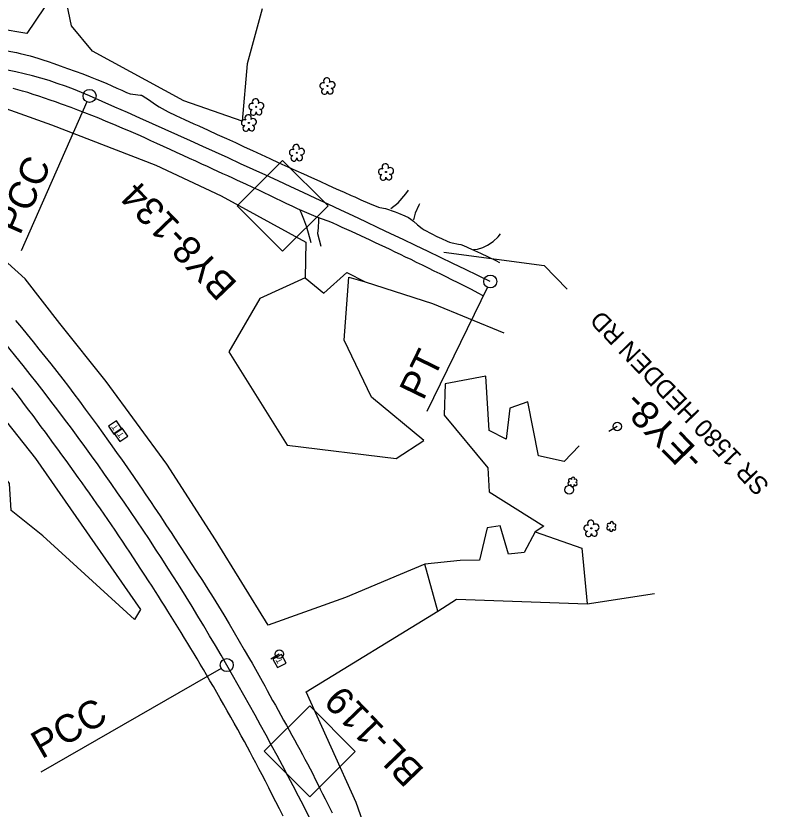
# Model space of a CAD drawing. Extents: x 473158 to 477500, y 500738 to 505114.
# Drawn here: x 475555.3 to 475990, y 502265.8 to 502723.9 of the extents above; entities that cross this region are included whole.
import ezdxf

# ---------------------------------------------------------------- set-up
doc = ezdxf.new("R2010")
doc.units = 0
for name, color, linetype in [('CTL Secondary Horizontal and Vertical CELL', 7, 'Continuous'), ('CTL Secondary Horizontal and Vertical Leader', 7, 'Continuous'), ('CTL Secondary Horizontal and Vertical Text', 7, 'Continuous'), ('Exist Horizontal Alignment', 7, 'Continuous'), ('Exist Horizontal Alignment Direction Label', 7, 'Continuous'), ('Exist Other Culture Well CELL', 7, 'Continuous'), ('Exist Roads EOP', 7, 'Continuous'), ('Exist Roads EOP Text', 7, 'Continuous'), ('Exist Roads Soil', 7, 'Continuous'), ('Exist Utilities Power Pole CELL', 7, 'Continuous'), ('Exist Utilities Telephone Pedestal CELL', 7, 'Continuous'), ('Exist Vegetation Hedge Row', 7, 'Continuous'), ('Exist Vegetation Shrub CELL', 7, 'Continuous'), ('Exist Vegetation Tree CELL', 7, 'Continuous'), ('Exist Vegetation Woods Line', 7, 'Continuous')]:
    doc.layers.add(name, color=color, linetype=linetype)

msp = doc.modelspace()

# ---------------------------------------------------------------- linework, layer by layer
at = {"layer": 'CTL Secondary Horizontal and Vertical CELL'}
for p, q in [((475709.09, 502614.11), (475709.09, 502614.11)), ((475724.77, 502299.1), (475724.77, 502299.1))]:
    msp.add_line(p, q, dxfattribs=at)
for points in [[(475683.01, 502614.2), (475709.22, 502640.4), (475735.47, 502614.15), (475709.26, 502587.94)], [(475698.7, 502299.19), (475724.9, 502325.39), (475751.16, 502299.14), (475724.95, 502272.93)]]:
    msp.add_lwpolyline(points, close=True, dxfattribs=at)
at = {"layer": 'CTL Secondary Horizontal and Vertical Leader'}
msp.add_lwpolyline([(475802.27, 502587.46), (475860.17, 502579.73), (475873.39, 502565.98)], dxfattribs=at)
at = {"layer": 'Exist Horizontal Alignment'}
for p, q in [((475596.32, 502674.23), (475558.36, 502588.14)), ((475827.45, 502567.1), (475792.56, 502495.4)), ((475673.81, 502347.07), (475569.78, 502287.2))]:
    msp.add_line(p, q, dxfattribs=at)
for centre in [(475597.83, 502677.66), (475829.09, 502570.47), (475677.06, 502348.94)]:
    msp.add_circle(centre, 3.75, dxfattribs=at)
for centre, radius, start, end in [((475506.78, 502471.14), 225.7, 66.2091, 86.4527), ((472863.49, 496475.42), 6778.23, 64.054428, 66.209138), ((474463.75, 501650.77), 1399.85, 29.91717, 47.05976), ((473989.37, 501377.8), 1947.16, 23.67637, 29.91717)]:
    msp.add_arc(centre, radius, start, end, dxfattribs=at)
at = {"layer": 'Exist Other Culture Well CELL'}
msp.add_circle((475874.64, 502450.21), 2.56, dxfattribs=at)
at = {"layer": 'Exist Roads EOP'}
for points in [[(475550.28, 502703.71), (475555.6, 502702.62), (475557.78, 502702.16), (475563.57, 502700.75), (475568.08, 502699.39), (475570.86, 502698.49), (475573.95, 502697.47), (475577.27, 502696.34), (475580.97, 502695.05), (475585.2, 502693.53), (475589.63, 502691.91), (475593.94, 502690.31), (475598.1, 502688.72), (475602.09, 502687.14), (475607.5, 502684.91), (475610.64, 502683.55), (475613.64, 502682.2), (475616.42, 502680.91), (475619.11, 502679.68), (475621.33, 502678.9), (475622.88, 502678.57), (475627.31, 502678.15), (475627.63, 502678.09), (475627.8, 502678.03), (475628.19, 502677.86), (475632.36, 502675.11), (475635.29, 502673.1), (475638.05, 502671.3), (475643.15, 502668.45), (475647.7, 502666.23), (475652.66, 502664), (475658.08, 502661.6), (475660.85, 502660.36), (475666.25, 502657.88), (475671.56, 502655.43), (475676.86, 502653.02), (475682.05, 502650.64), (475687.07, 502648.31), (475691.97, 502646.02), (475696.83, 502643.75), (475701.83, 502641.44), (475707.14, 502639), (475712.32, 502636.64), (475716.94, 502634.56), (475721.37, 502632.56), (475725.99, 502630.47), (475730.73, 502628.32), (475735.53, 502626.17), (475740.23, 502624.07), (475744.71, 502622.06), (475748.89, 502620.17), (475750.84, 502619.29), (475754.43, 502617.66), (475759.41, 502615.45), (475764.5, 502613.44), (475765.33, 502613.22), (475768.69, 502612.64), (475774.15, 502610.73), (475776.13, 502609.95), (475779.72, 502608.42), (475781.92, 502607.33), (475783.3, 502606.47), (475784.88, 502605.27), (475787.13, 502603.28), (475789.77, 502601.03), (475791.02, 502600.24), (475795.34, 502598.04), (475798.34, 502596.51), (475800.92, 502595.23), (475804.19, 502593.68), (475805.63, 502593.13), (475807.03, 502592.74), (475810.8, 502592.09), (475812.1, 502591.76), (475813.68, 502591.24), (475818.24, 502589.21), (475823.54, 502586.75), (475827.94, 502584.67), (475832.32, 502582.54), (475834.5, 502581.47)], [(475825, 502562.27), (475822.2, 502563.71), (475818.23, 502565.76), (475814.34, 502567.75), (475810.6, 502569.65), (475807, 502571.46), (475803.55, 502573.18), (475800.17, 502574.85), (475796.78, 502576.52), (475793.38, 502578.19), (475789.97, 502579.86), (475786.61, 502581.5), (475783.37, 502583.08), (475780.24, 502584.59), (475777.22, 502586.04), (475774.26, 502587.45), (475771.31, 502588.85), (475768.36, 502590.24), (475765.42, 502591.62), (475762.53, 502592.98), (475759.71, 502594.29), (475754.31, 502596.81), (475749.03, 502599.25), (475743.69, 502601.71), (475741.27, 502602.83), (475738.03, 502604.31), (475735.61, 502605.36), (475731.67, 502606.61), (475728.59, 502607.8), (475723.21, 502610.1), (475717.75, 502612.5), (475714.76, 502613.88), (475711.69, 502615.33), (475708.54, 502616.82), (475705.28, 502618.4), (475701.94, 502620.06), (475698.7, 502621.63), (475695.52, 502623.12), (475691.99, 502624.76), (475687.98, 502626.62), (475683.19, 502628.83), (475680.48, 502630.08), (475677.64, 502631.39), (475674.77, 502632.71), (475671.86, 502634.04), (475668.91, 502635.39), (475665.85, 502636.8), (475662.6, 502638.29), (475659.17, 502639.87), (475655.55, 502641.53), (475651.83, 502643.25), (475648.07, 502644.98), (475644.28, 502646.73), (475640.45, 502648.49), (475636.74, 502650.19), (475633.29, 502651.75), (475630.11, 502653.19), (475627.19, 502654.49), (475621.78, 502656.87), (475616.69, 502659.06), (475611.91, 502661.08), (475607.41, 502662.95), (475603.15, 502664.7), (475599.08, 502666.33), (475595.11, 502667.88), (475591.17, 502669.4), (475587.29, 502670.86), (475581.7, 502672.93), (475578.28, 502674.16), (475575.12, 502675.25), (475571.9, 502676.33), (475568.6, 502677.43), (475565.35, 502678.5), (475562.2, 502679.54), (475559.17, 502680.45), (475553.7, 502681.87)], [(475555.07, 502548.03), (475558.49, 502543.9), (475561.88, 502539.79), (475565.27, 502535.64), (475568.65, 502531.45), (475572.03, 502527.23), (475575.46, 502522.93), (475578.97, 502518.48), (475582.42, 502514.06), (475585.63, 502509.85), (475588.77, 502505.65), (475592, 502501.31), (475595.32, 502496.81), (475598.73, 502492.16), (475602.14, 502487.48), (475605.45, 502482.9), (475608.84, 502478.18), (475610.63, 502475.66), (475612.49, 502473.05), (475614.36, 502470.41), (475616.19, 502467.83), (475617.97, 502465.3), (475619.71, 502462.82), (475623.12, 502457.9), (475626.51, 502452.97), (475628.2, 502450.48), (475629.91, 502447.95), (475631.64, 502445.4), (475633.39, 502442.81), (475635.14, 502440.21), (475636.87, 502437.63), (475638.58, 502435.08), (475640.27, 502432.54), (475641.95, 502430.01), (475643.61, 502427.49), (475645.26, 502424.96), (475646.88, 502422.43), (475650.12, 502417.41), (475653.33, 502412.48), (475656.53, 502407.58), (475659.74, 502402.68), (475662.94, 502397.77), (475666.13, 502392.85), (475669.26, 502387.92), (475672.34, 502382.96), (475675.36, 502377.94), (475678.35, 502372.82), (475681.3, 502367.73), (475684.18, 502362.76), (475687.08, 502357.78), (475690.08, 502352.64), (475691.59, 502350.03), (475694.54, 502344.84), (475697.43, 502339.64), (475698.91, 502336.97), (475700.41, 502334.23), (475701.95, 502331.42), (475703.51, 502328.58), (475705.08, 502325.74), (475706.65, 502322.89), (475708.24, 502320.04), (475709.84, 502317.18), (475711.42, 502314.32), (475713.01, 502311.45), (475714.6, 502308.58), (475716.16, 502305.73), (475717.7, 502302.92), (475719.21, 502300.15), (475720.69, 502297.42), (475722.15, 502294.68), (475723.63, 502291.88), (475725.11, 502289.01), (475726.6, 502286.09), (475728.08, 502283.15), (475729.54, 502280.26), (475730.96, 502277.4), (475732.36, 502274.58), (475733.74, 502271.79), (475735.11, 502269.02), (475736.48, 502266.28), (475737.85, 502263.56)], [(475709.55, 502261.7), (475707.42, 502265.91), (475705.32, 502270.05), (475703.25, 502274.11), (475701.24, 502278.04), (475699.29, 502281.85), (475697.39, 502285.54), (475695.55, 502289.08), (475693.8, 502292.44), (475692.12, 502295.62), (475690.53, 502298.62), (475688.91, 502301.62), (475687.18, 502304.81), (475685.33, 502308.19), (475683.36, 502311.74), (475681.34, 502315.38), (475679.31, 502318.98), (475677.29, 502322.55), (475675.28, 502326.09), (475673.27, 502329.6), (475671.27, 502333.08), (475669.3, 502336.52), (475667.33, 502339.93), (475665.4, 502343.26), (475663.53, 502346.47), (475661.7, 502349.56), (475659.93, 502352.53), (475658.16, 502355.46), (475656.35, 502358.45), (475654.5, 502361.49), (475652.6, 502364.58), (475650.69, 502367.7), (475648.77, 502370.82), (475646.86, 502373.92), (475644.94, 502377.02), (475643.05, 502380.07), (475641.21, 502383.03), (475639.41, 502385.89), (475637.66, 502388.67), (475635.87, 502391.48), (475633.95, 502394.47), (475631.9, 502397.63), (475629.73, 502400.97), (475627.5, 502404.36), (475625.31, 502407.69), (475623.16, 502410.95), (475621.04, 502414.16), (475618.94, 502417.32), (475616.84, 502420.48), (475614.73, 502423.64), (475612.62, 502426.78), (475610.5, 502429.91), (475608.39, 502433.02), (475606.28, 502436.09), (475604.18, 502439.13), (475602.07, 502442.16), (475599.95, 502445.18), (475597.82, 502448.2), (475595.68, 502451.21), (475593.51, 502454.26), (475591.28, 502457.38), (475588.99, 502460.57), (475586.64, 502463.84), (475584.26, 502467.13), (475581.88, 502470.42), (475579.5, 502473.69), (475577.11, 502476.94), (475574.73, 502480.19), (475572.35, 502483.41), (475569.98, 502486.63), (475567.61, 502489.82), (475565.23, 502493.02), (475562.83, 502496.23), (475560.39, 502499.44), (475557.92, 502502.67), (475555.44, 502505.89), (475552.96, 502509.1)]]:
    msp.add_lwpolyline(points, dxfattribs=at)
at = {"layer": 'Exist Roads Soil'}
for points in [[(475771.67, 502612.56), (475775.95, 502615.94), (475780.34, 502621), (475781.98, 502623.28)], [(475788.21, 502615.34), (475787.84, 502614.63), (475785.69, 502609.93), (475784.75, 502606.06)], [(475725.71, 502592.84), (475723.2, 502601.93), (475721.5, 502606.47), (475720.04, 502610.35), (475719.47, 502611.56)], [(475730.03, 502607.12), (475729.97, 502605.66), (475729.7, 502601.49), (475729.44, 502598.11), (475731.33, 502590.87)], [(475819.44, 502588.97), (475821.81, 502589.18), (475824.73, 502590.07), (475827.53, 502591.44), (475830.82, 502593.58), (475833.61, 502596.25), (475834.96, 502597.94)]]:
    msp.add_lwpolyline(points, dxfattribs=at)
at = {"layer": 'Exist Utilities Power Pole CELL'}
for p, q in [((475902.41, 502486.72), (475897.59, 502483.82)), ((475902.41, 502486.72), (475902.41, 502486.72)), ((475707.36, 502355.28), (475702.53, 502352.39)), ((475707.36, 502355.28), (475707.36, 502355.28))]:
    msp.add_line(p, q, dxfattribs=at)
for centre in [(475902.41, 502486.72), (475707.36, 502355.28)]:
    msp.add_circle(centre, 2.45, dxfattribs=at)
at = {"layer": 'Exist Utilities Telephone Pedestal CELL'}
for p, q in [((475612.65, 502486.12), (475612.65, 502486.12)), ((475615.96, 502481.85), (475615.96, 502481.85)), ((475707.45, 502351.21), (475707.45, 502351.21))]:
    msp.add_line(p, q, dxfattribs=at)
for points in [[(475616.52, 502485.47), (475613.36, 502490.08), (475608.75, 502486.92), (475611.91, 502482.3), (475616.52, 502485.47)], [(475619.84, 502481.24), (475616.62, 502485.82), (475612.05, 502482.6), (475615.26, 502478.03), (475619.84, 502481.24)], [(475711.23, 502350.17), (475708.56, 502355.08), (475703.64, 502352.41), (475706.32, 502347.5), (475711.23, 502350.17)]]:
    msp.add_lwpolyline(points, dxfattribs=at)
at = {"layer": 'Exist Vegetation Hedge Row'}
msp.add_line((475798.79, 502380.12), (475791.38, 502407.22), dxfattribs=at)
for points in [[(475722.35, 502572.6), (475733.09, 502563.69), (475746.35, 502575.71), (475756.93, 502570.21)], [(475855.05, 502425.98), (475881.96, 502416.49), (475884.97, 502384.38)]]:
    msp.add_lwpolyline(points, dxfattribs=at)
at = {"layer": 'Exist Vegetation Shrub CELL'}
for p, q in [((475876.63, 502454.53), (475876.63, 502454.53)), ((475899.04, 502428.76), (475899.04, 502428.76))]:
    msp.add_line(p, q, dxfattribs=at)
for centre, radius, start, end in [((475875.15, 502455.66), 0.968, 35.8908, 245.4216), ((475876.86, 502456.57), 0.99, 334.8391, 200.4717), ((475874.83, 502453.83), 0.955, 95.1099, 327.9534), ((475876.5, 502452.85), 0.984, 151.2797, 21.387), ((475878.27, 502453.6), 0.937, 204.9913, 73.4601), ((475878.3, 502455.4), 0.929, 284.4567, 126.0861), ((475897.55, 502429.89), 0.968, 35.8908, 245.4216), ((475899.27, 502430.8), 0.99, 334.8391, 200.4717), ((475900.71, 502429.63), 0.929, 284.4567, 126.0861), ((475897.24, 502428.06), 0.955, 95.1099, 327.9534), ((475898.91, 502427.08), 0.984, 151.2797, 21.387), ((475900.67, 502427.83), 0.937, 204.9913, 73.4601)]:
    msp.add_arc(centre, radius, start, end, dxfattribs=at)
at = {"layer": 'Exist Vegetation Tree CELL'}
for p, q in [((475735.11, 502683.36), (475735.11, 502683.36)), ((475694.01, 502671.3), (475694.01, 502671.3)), ((475689.76, 502662.02), (475689.76, 502662.02)), ((475717.46, 502644.82), (475717.46, 502644.82)), ((475768.89, 502633.72), (475768.89, 502633.72)), ((475887.45, 502427.94), (475887.45, 502427.94))]:
    msp.add_line(p, q, dxfattribs=at)
for centre in [(475735.11, 502683.36), (475694.01, 502671.3), (475689.76, 502662.02), (475717.46, 502644.82), (475768.89, 502633.72), (475887.45, 502427.94)]:
    msp.add_circle(centre, 0.326, dxfattribs=at)
for centre, radius, start, end in [((475734.72, 502686.24), 1.86, 330.1651, 219.7134), ((475737.66, 502683.95), 1.9, 257.1011, 134.1999), ((475732.5, 502683.52), 1.73, 62.6636, 279.3457), ((475733.4, 502680.24), 1.69, 111.5671, 6.231), ((475736.78, 502680.46), 1.7, 181.2822, 74.56), ((475691.4, 502671.46), 1.73, 62.6636, 279.3457), ((475693.63, 502674.17), 1.86, 330.1651, 219.7134), ((475696.56, 502671.89), 1.9, 257.1011, 134.1999), ((475692.31, 502668.18), 1.69, 111.5671, 6.231), ((475695.68, 502668.4), 1.7, 181.2822, 74.56), ((475687.16, 502662.17), 1.73, 62.6636, 279.3457), ((475689.38, 502664.89), 1.86, 330.1651, 219.7134), ((475692.31, 502662.61), 1.9, 257.1011, 134.1999), ((475688.06, 502658.9), 1.69, 111.5671, 6.231), ((475691.44, 502659.12), 1.7, 181.2822, 74.56), ((475717.07, 502647.69), 1.86, 330.1651, 219.7134), ((475714.85, 502644.97), 1.73, 62.6636, 279.3457), ((475720.01, 502645.41), 1.9, 257.1011, 134.1999), ((475715.75, 502641.7), 1.69, 111.5671, 6.231), ((475719.13, 502641.92), 1.7, 181.2822, 74.56), ((475766.28, 502633.87), 1.73, 62.6636, 279.3457), ((475768.5, 502636.59), 1.86, 330.1651, 219.7134), ((475771.44, 502634.31), 1.9, 257.1011, 134.1999), ((475767.18, 502630.6), 1.69, 111.5671, 6.231), ((475770.56, 502630.82), 1.7, 181.2822, 74.56), ((475884.85, 502428.09), 1.73, 62.6636, 279.3457), ((475887.07, 502430.81), 1.86, 330.1651, 219.7134), ((475890, 502428.53), 1.9, 257.1011, 134.1999), ((475885.75, 502424.82), 1.69, 111.5671, 6.231), ((475889.13, 502425.04), 1.7, 181.2822, 74.56)]:
    msp.add_arc(centre, radius, start, end, dxfattribs=at)
at = {"layer": 'Exist Vegetation Woods Line'}
for points in [[(475697.4, 502727.92), (475688.86, 502696.09), (475686, 502663.11), (475652.17, 502674.74), (475599.58, 502703.42), (475587.38, 502718.1), (475582.11, 502744.06), (475561.68, 502713.66), (475513.63, 502721.78), (475505.24, 502738.53), (475493.85, 502754.4), (475471.86, 502759.83), (475461.5, 502741.2), (475477.48, 502717.68), (475433.11, 502713.77), (475407.41, 502728.53), (475369.2, 502759.84), (475334.77, 502792.14), (475288.78, 502817.79), (475268.13, 502832.08), (475231.22, 502863.61), (475223.58, 502870.17), (475227.24, 502912), (475230.74, 502956.28)], [(475560.77, 502571.96), (475514.76, 502613.46), (475492.24, 502638.09), (475487.3, 502661.49), (475487.62, 502674.6), (475491.52, 502676.65), (475531.03, 502676.82), (475575.86, 502660.99), (475636.13, 502637.63), (475673.71, 502619.9)], [(475673.71, 502619.9), (475722.61, 502593.24), (475722.35, 502572.6), (475696.14, 502560.61), (475678.22, 502529.9), (475711.93, 502476.05), (475774.8, 502468.3), (475790.68, 502478.65), (475760.55, 502503.66), (475744.84, 502536.53), (475747.5, 502572.89), (475756.93, 502570.21), (475795.73, 502557.68), (475836.96, 502540.75)], [(475880.4, 502475.57), (475871.81, 502466.51), (475856.96, 502469.71), (475850.79, 502501.04), (475840.42, 502497.23), (475838.17, 502479.44), (475828.46, 502484.38), (475826.54, 502515.83), (475803.05, 502511.42), (475802.39, 502493.24), (475827.65, 502462.87), (475828.41, 502449.05), (475860, 502429.23), (475855.05, 502425.98), (475848.64, 502414.05), (475839.61, 502412.93), (475834.81, 502429.44), (475827.24, 502428.13), (475822.78, 502409.55), (475811.81, 502409.42), (475791.38, 502407.22), (475777.11, 502401.23), (475745.51, 502387.9), (475700.84, 502372.1), (475670.5, 502421.23), (475642.53, 502465.06), (475607.44, 502512.69), (475580.6, 502546.14), (475560.77, 502571.96)], [(475519.21, 502528.11), (475566.55, 502468.17), (475627.31, 502380.99), (475623.71, 502375.33), (475570.95, 502423.65), (475552.52, 502438.18), (475551.71, 502453.86), (475513.44, 502504.97), (475506.23, 502511.15), (475478.72, 502478.44), (475471.69, 502459.66), (475471.56, 502419.97), (475490.82, 502357.44), (475486.63, 502347.37), (475481.08, 502349.43), (475426.9, 502485.3)], [(475886.38, 502172.36), (475869.39, 502179.12), (475858.65, 502175.9), (475846.51, 502149.47), (475826.98, 502124.47), (475814.74, 502146.78), (475811.61, 502158.67), (475812.53, 502198.84), (475810.93, 502216.74), (475793.33, 502227.19), (475795.06, 502187.54), (475786, 502184.24), (475774.11, 502205.93), (475751.7, 502269.54), (475722.89, 502333.61), (475798.79, 502380.12), (475809.6, 502387.08), (475884.97, 502384.38), (475923.94, 502390.38)]]:
    msp.add_lwpolyline(points, dxfattribs=at)

# ---------------------------------------------------------------- texts
at = {"layer": 'CTL Secondary Horizontal and Vertical Text'}
for s, p in [('BY8-134', (475683.75, 502569.33)), ('BL-119', (475791.65, 502288.41))]:
    msp.add_text(s, height=16, rotation=133.8723, dxfattribs=at).set_placement(p)
at = {"layer": 'Exist Horizontal Alignment'}
for s, rotation, p in [('PCC', 66.2091, (475557.7, 502596.76)), ('PT', 64.0544, (475790.39, 502501.25)), ('PCC', 29.9172, (475570.22, 502294.47))]:
    msp.add_text(s, height=16, rotation=rotation, dxfattribs=at).set_placement(p)
at = {"layer": 'Exist Horizontal Alignment Direction Label'}
msp.add_text('-EY8-', height=16, rotation=134.4581, dxfattribs=at).set_placement((475953.37, 502469.32))
at = {"layer": 'Exist Roads EOP Text'}
msp.add_text('SR 1580 HEDDEN RD', height=10.4, rotation=133.8722, dxfattribs=at).set_placement((475990.73, 502453.08))
at = {"layer": 'Exist Utilities Telephone Pedestal CELL'}
for rotation, p in [(124.4133, (475614.7, 502486.15)), (125.0601, (475618.01, 502481.9)), (118.57, (475709.49, 502351.04))]:
    msp.add_text('T', height=3.42, rotation=rotation, dxfattribs=at).set_placement(p)

doc.saveas('drawing.dxf')
